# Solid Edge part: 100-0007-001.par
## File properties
Title: 100-0007-00.par
Author: rkriggs
Template: Normal.par
Last saved by: jccrumbl
Revision: 39
Application: Solid Edge
Revision: A
Teamcenter Item Type: Item
Accuracy: 0.99
TC Engineering Description: Valve Handle Cover
TC_ImportTime: 2008-07-08
PartType: -
Last Saved Version: -
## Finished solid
Body 1: solid body, 20 faces, 38 edges, 20 vertices.
  Faces by surface: cylinder 9, plane 7, sphere 4
  Edges by curve: line 20, circle 18
Bounding box of the edges (mm; curved faces can reach further): 60.000 x 24.000 x 14.000, from (0, -12, -7) to (60, 12, 7).
Cylindrical faces by radius (mm): R2.5 x1, R5 x8
Spherical faces by radius (mm): R5 x4
Planar faces by outward normal: +x 1, +y 1, +z 1, -x 2, -y 1, -z 1
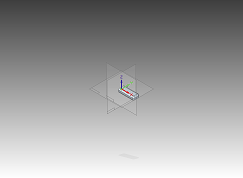
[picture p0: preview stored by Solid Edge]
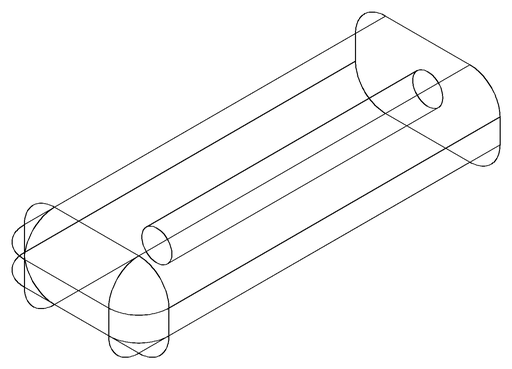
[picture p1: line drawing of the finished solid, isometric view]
